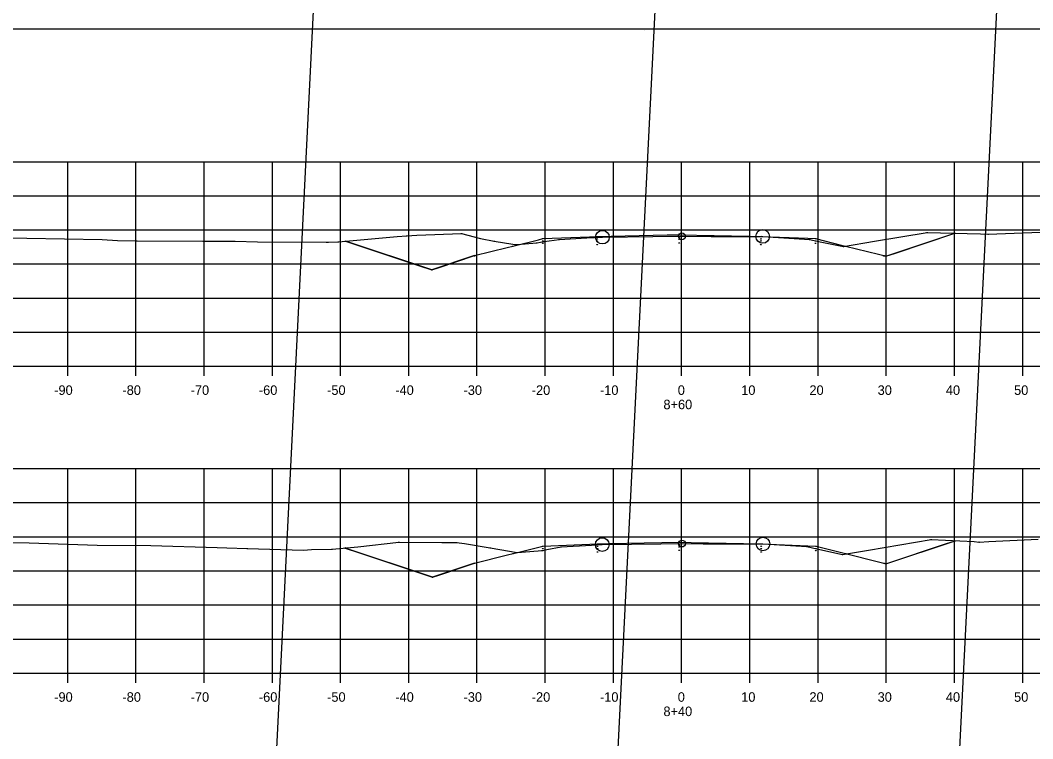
# Model space of a CAD drawing. Extents: x 1300404 to 1323571, y 234004 to 252077.
# Drawn here: x 1315620.3 to 1315768.7, y 242873.8 to 242979.2 of the extents above; entities that cross this region are included whole.
import ezdxf

# ---------------------------------------------------------------- set-up
doc = ezdxf.new("R2010")
doc.units = 0
for name, color, linetype in [('Default', 7, 'Continuous'), ('R_Axis', 7, 'Continuous'), ('R_Axis Annot', 7, 'Continuous'), ('R_Border', 7, 'Continuous'), ('R_Draft', 7, 'Continuous'), ('R_Exist Surface', 7, 'Continuous'), ('R_Fin Surface', 7, 'Continuous'), ('R_Floodway', 7, 'Continuous'), ('R_Grid', 7, 'Continuous'), ('R_No Plot', 7, 'Continuous')]:
    doc.layers.add(name, color=color, linetype=linetype)

msp = doc.modelspace()

# ---------------------------------------------------------------- linework, layer by layer
at = {"layer": 'Default'}
msp.add_line((1315559.28, 242977.92), (1315875.46, 242977.92), dxfattribs=at)
at = {"layer": 'R_Axis'}
for p, q in [((1315577.28, 242928.46), (1315857.28, 242928.46)), ((1315627.28, 242927.06), (1315627.28, 242928.46)), ((1315637.28, 242927.06), (1315637.28, 242928.46)), ((1315647.28, 242927.06), (1315647.28, 242928.46)), ((1315657.28, 242927.06), (1315657.28, 242928.46)), ((1315667.28, 242927.06), (1315667.28, 242928.46)), ((1315677.28, 242927.06), (1315677.28, 242928.46)), ((1315687.28, 242927.06), (1315687.28, 242928.46)), ((1315697.28, 242927.06), (1315697.28, 242928.46)), ((1315707.28, 242927.06), (1315707.28, 242928.46)), ((1315717.28, 242927.06), (1315717.28, 242928.46)), ((1315727.28, 242927.06), (1315727.28, 242928.46)), ((1315737.28, 242927.06), (1315737.28, 242928.46)), ((1315747.28, 242927.06), (1315747.28, 242928.46)), ((1315757.28, 242927.06), (1315757.28, 242928.46)), ((1315767.28, 242927.06), (1315767.28, 242928.46)), ((1315577.28, 242883.46), (1315857.28, 242883.46)), ((1315627.28, 242882.06), (1315627.28, 242883.46)), ((1315637.28, 242882.06), (1315637.28, 242883.46)), ((1315647.28, 242882.06), (1315647.28, 242883.46)), ((1315657.28, 242882.06), (1315657.28, 242883.46)), ((1315667.28, 242882.06), (1315667.28, 242883.46)), ((1315677.28, 242882.06), (1315677.28, 242883.46)), ((1315687.28, 242882.06), (1315687.28, 242883.46)), ((1315697.28, 242882.06), (1315697.28, 242883.46)), ((1315707.28, 242882.06), (1315707.28, 242883.46)), ((1315717.28, 242882.06), (1315717.28, 242883.46)), ((1315727.28, 242882.06), (1315727.28, 242883.46)), ((1315737.28, 242882.06), (1315737.28, 242883.46)), ((1315747.28, 242882.06), (1315747.28, 242883.46)), ((1315757.28, 242882.06), (1315757.28, 242883.46)), ((1315767.28, 242882.06), (1315767.28, 242883.46))]:
    msp.add_line(p, q, dxfattribs=at)
at = {"layer": 'R_Border'}
msp.add_line((1315711.8, 242977.66), (1315711.8, 242977.66), dxfattribs=at)
msp.add_line((1315711.8, 242977.66), (1315711.8, 242977.66), dxfattribs=at)
at = {"layer": 'R_Draft'}
for points in [[(1315637.35, 242946.91), (1315637.4, 242946.81), (1315637.3, 242946.81)], [(1315668.02, 242946.87), (1315668.07, 242946.77), (1315667.97, 242946.77)], [(1315668.02, 242946.87), (1315668.07, 242946.77), (1315667.97, 242946.77)], [(1315677, 242947.65), (1315677.05, 242947.55), (1315676.95, 242947.55)], [(1315685.02, 242947.98), (1315685.07, 242947.88), (1315684.97, 242947.88)], [(1315696.91, 242947.23), (1315696.96, 242947.13), (1315696.86, 242947.13)], [(1315696.91, 242946.9), (1315696.96, 242946.8), (1315696.86, 242946.8)], [(1315699.33, 242947.12), (1315699.38, 242947.02), (1315699.28, 242947.02)], [(1315704.91, 242947.55), (1315704.96, 242947.45), (1315704.86, 242947.45)], [(1315704.91, 242947.22), (1315704.96, 242947.12), (1315704.86, 242947.12)], [(1315704.91, 242946.88), (1315704.96, 242946.78), (1315704.86, 242946.78)], [(1315716.91, 242947.79), (1315716.96, 242947.69), (1315716.86, 242947.69)], [(1315716.91, 242947.46), (1315716.96, 242947.36), (1315716.86, 242947.36)], [(1315716.91, 242947.13), (1315716.96, 242947.03), (1315716.86, 242947.03)], [(1315728.91, 242947.55), (1315728.96, 242947.45), (1315728.86, 242947.45)], [(1315728.91, 242947.22), (1315728.96, 242947.12), (1315728.86, 242947.12)], [(1315728.91, 242946.89), (1315728.96, 242946.79), (1315728.86, 242946.79)], [(1315736.04, 242947.11), (1315736.09, 242947.01), (1315735.99, 242947.01)], [(1315736.91, 242947.23), (1315736.96, 242947.13), (1315736.86, 242947.13)], [(1315736.91, 242946.9), (1315736.96, 242946.8), (1315736.86, 242946.8)], [(1315753.27, 242948.12), (1315753.32, 242948.02), (1315753.22, 242948.02)], [(1315757.34, 242948.02), (1315757.39, 242947.92), (1315757.29, 242947.92)], [(1315757.34, 242948.02), (1315757.39, 242947.92), (1315757.29, 242947.92)], [(1315762.19, 242947.89), (1315762.24, 242947.79), (1315762.14, 242947.79)], [(1315666.98, 242946.78), (1315667.03, 242946.68), (1315666.93, 242946.68)], [(1315689.81, 242946.85), (1315689.86, 242946.75), (1315689.76, 242946.75)], [(1315692.54, 242946.14), (1315692.59, 242946.04), (1315692.49, 242946.04)], [(1315692.87, 242946.36), (1315692.92, 242946.26), (1315692.82, 242946.26)], [(1315696.03, 242946.59), (1315696.08, 242946.49), (1315695.98, 242946.49)], [(1315696.91, 242946.57), (1315696.96, 242946.47), (1315696.86, 242946.47)], [(1315704.91, 242946.38), (1315704.96, 242946.28), (1315704.86, 242946.28)], [(1315716.91, 242946.62), (1315716.96, 242946.52), (1315716.86, 242946.52)], [(1315728.91, 242946.38), (1315728.96, 242946.28), (1315728.86, 242946.28)], [(1315736.91, 242946.57), (1315736.96, 242946.47), (1315736.86, 242946.47)], [(1315741, 242946.09), (1315741.05, 242945.99), (1315740.95, 242945.99)], [(1315741.29, 242946.14), (1315741.34, 242946.04), (1315741.24, 242946.04)], [(1315686.91, 242944.73), (1315686.96, 242944.63), (1315686.86, 242944.63)], [(1315746.91, 242944.73), (1315746.96, 242944.63), (1315746.86, 242944.63)], [(1315747.2, 242944.64), (1315747.25, 242944.54), (1315747.15, 242944.54)], [(1315680.67, 242942.65), (1315680.72, 242942.55), (1315680.62, 242942.55)], [(1315675.8, 242902.7), (1315675.85, 242902.6), (1315675.75, 242902.6)], [(1315684.29, 242902.68), (1315684.34, 242902.58), (1315684.24, 242902.58)], [(1315704.93, 242902.46), (1315704.98, 242902.36), (1315704.88, 242902.36)], [(1315716.93, 242902.7), (1315716.98, 242902.6), (1315716.88, 242902.6)], [(1315716.93, 242902.37), (1315716.98, 242902.27), (1315716.88, 242902.27)], [(1315728.93, 242902.46), (1315728.98, 242902.36), (1315728.88, 242902.36)], [(1315753.85, 242903.09), (1315753.9, 242902.99), (1315753.8, 242902.99)], [(1315757.37, 242902.93), (1315757.42, 242902.83), (1315757.32, 242902.83)], [(1315757.37, 242902.93), (1315757.42, 242902.83), (1315757.32, 242902.83)], [(1315760.89, 242902.74), (1315760.94, 242902.64), (1315760.84, 242902.64)], [(1315653.61, 242901.78), (1315653.66, 242901.68), (1315653.56, 242901.68)], [(1315666.06, 242901.68), (1315666.11, 242901.58), (1315666.01, 242901.58)], [(1315667.98, 242901.86), (1315668.03, 242901.76), (1315667.93, 242901.76)], [(1315667.98, 242901.86), (1315668.03, 242901.76), (1315667.93, 242901.76)], [(1315689.19, 242901.88), (1315689.24, 242901.78), (1315689.14, 242901.78)], [(1315692.56, 242901.05), (1315692.61, 242900.95), (1315692.51, 242900.95)], [(1315693.19, 242901.21), (1315693.24, 242901.11), (1315693.14, 242901.11)], [(1315696.85, 242901.49), (1315696.9, 242901.39), (1315696.8, 242901.39)], [(1315696.93, 242902.14), (1315696.98, 242902.04), (1315696.88, 242902.04)], [(1315696.93, 242901.81), (1315696.98, 242901.71), (1315696.88, 242901.71)], [(1315696.93, 242901.48), (1315696.98, 242901.38), (1315696.88, 242901.38)], [(1315699.63, 242902.04), (1315699.68, 242901.94), (1315699.58, 242901.94)], [(1315704.93, 242902.13), (1315704.98, 242902.03), (1315704.88, 242902.03)], [(1315704.93, 242901.8), (1315704.98, 242901.7), (1315704.88, 242901.7)], [(1315704.93, 242901.3), (1315704.98, 242901.2), (1315704.88, 242901.2)], [(1315716.93, 242902.04), (1315716.98, 242901.94), (1315716.88, 242901.94)], [(1315716.93, 242901.54), (1315716.98, 242901.44), (1315716.88, 242901.44)], [(1315728.93, 242902.13), (1315728.98, 242902.03), (1315728.88, 242902.03)], [(1315728.93, 242901.8), (1315728.98, 242901.7), (1315728.88, 242901.7)], [(1315728.93, 242901.3), (1315728.98, 242901.2), (1315728.88, 242901.2)], [(1315735.62, 242902.08), (1315735.67, 242901.98), (1315735.57, 242901.98)], [(1315736.93, 242902.14), (1315736.98, 242902.04), (1315736.88, 242902.04)], [(1315736.93, 242901.81), (1315736.98, 242901.71), (1315736.88, 242901.71)], [(1315736.93, 242901.48), (1315736.98, 242901.38), (1315736.88, 242901.38)], [(1315740.85, 242900.92), (1315740.9, 242900.82), (1315740.8, 242900.82)], [(1315741.31, 242901.05), (1315741.36, 242900.95), (1315741.26, 242900.95)], [(1315686.93, 242899.64), (1315686.98, 242899.54), (1315686.88, 242899.54)], [(1315746.93, 242899.64), (1315746.98, 242899.54), (1315746.88, 242899.54)], [(1315747.22, 242899.55), (1315747.27, 242899.45), (1315747.17, 242899.45)], [(1315680.77, 242897.59), (1315680.82, 242897.49), (1315680.72, 242897.49)]]:
    msp.add_lwpolyline(points, close=True, dxfattribs=at)
at = {"layer": 'R_Exist Surface'}
for points in [[(1315615.71, 242947.33), (1315632.36, 242947.05), (1315634.59, 242946.92), (1315637.35, 242946.86), (1315647.1, 242946.79), (1315651.82, 242946.82), (1315655.12, 242946.72), (1315665.16, 242946.64), (1315665.5, 242946.64), (1315666.98, 242946.73), (1315675.59, 242947.47), (1315677, 242947.6), (1315678.46, 242947.69), (1315685.02, 242947.93), (1315687.8, 242947.21), (1315689.81, 242946.8), (1315692.54, 242946.37), (1315692.87, 242946.31), (1315693.16, 242946.33), (1315696.03, 242946.54), (1315697.14, 242946.75), (1315699.33, 242947.07), (1315703.39, 242947.27), (1315705.67, 242947.39), (1315713.04, 242947.47), (1315717.31, 242947.52), (1315721.61, 242947.5), (1315729.16, 242947.5), (1315733.79, 242947.2), (1315736.04, 242947.06), (1315737.82, 242946.68), (1315741, 242946.04), (1315745.56, 242946.8), (1315753.27, 242948.07), (1315761.09, 242947.86), (1315762.19, 242947.84), (1315771.14, 242948.16)], [(1315610.92, 242902.73), (1315621.64, 242902.57), (1315631.58, 242902.21), (1315639.45, 242902.16), (1315649.2, 242901.86), (1315650.59, 242901.82), (1315653.61, 242901.73), (1315661.83, 242901.51), (1315663.03, 242901.57), (1315666.06, 242901.63), (1315669.83, 242901.99), (1315675.8, 242902.65), (1315682.15, 242902.6), (1315684.29, 242902.63), (1315685.47, 242902.47), (1315689.19, 242901.83), (1315692.04, 242901.36), (1315693.19, 242901.16), (1315693.8, 242901.21), (1315696.85, 242901.44), (1315697.51, 242901.6), (1315699.63, 242901.99), (1315704.05, 242902.22), (1315705.63, 242902.32), (1315714.21, 242902.42), (1315717.33, 242902.46), (1315720.45, 242902.43), (1315729.2, 242902.4), (1315730.82, 242902.32), (1315735.62, 242902.03), (1315737.08, 242901.69), (1315740.85, 242900.87), (1315744.69, 242901.51), (1315753.85, 242903.04), (1315760.14, 242902.75), (1315760.89, 242902.69), (1315762.29, 242902.75), (1315769.52, 242903.12)]]:
    msp.add_lwpolyline(points, dxfattribs=at)
at = {"layer": 'R_Fin Surface'}
for points in [[(1315668.02, 242946.82), (1315678.83, 242943.21), (1315680.67, 242942.6), (1315681.6, 242942.91), (1315686.91, 242944.68), (1315691.71, 242945.88), (1315692.54, 242946.09), (1315696.28, 242947.02), (1315696.91, 242947.18), (1315703.75, 242947.45), (1315704.91, 242947.5), (1315715.18, 242947.71), (1315716.91, 242947.74), (1315727.19, 242947.53), (1315728.91, 242947.5), (1315735.77, 242947.23), (1315736.91, 242947.18), (1315740.67, 242946.24), (1315741.29, 242946.09), (1315746.12, 242944.88), (1315746.91, 242944.68), (1315746.95, 242944.67), (1315747.2, 242944.59), (1315748.63, 242945.06), (1315757.34, 242947.97)], [(1315667.98, 242901.81), (1315669.89, 242901.17), (1315680.77, 242897.54), (1315681.69, 242897.84), (1315686.93, 242899.59), (1315691.73, 242900.79), (1315692.56, 242901), (1315693.2, 242901.16), (1315696.93, 242902.09), (1315698.1, 242902.14), (1315704.93, 242902.41), (1315706.67, 242902.45), (1315716.93, 242902.65), (1315718.66, 242902.62), (1315728.93, 242902.41), (1315730.08, 242902.37), (1315736.93, 242902.09), (1315737.56, 242901.94), (1315741.31, 242901), (1315746.14, 242899.79), (1315746.93, 242899.59), (1315746.97, 242899.58), (1315747.22, 242899.5), (1315755.94, 242902.41), (1315757.37, 242902.88)]]:
    msp.add_lwpolyline(points, dxfattribs=at)
at = {"layer": 'R_Floodway'}
for p, q in [((1315724.08, 242194.52), (1315766.53, 243041.85)), ((1315673.23, 242178.64), (1315715.45, 243021.54)), ((1315622.37, 242162.75), (1315664.37, 243001.24))]:
    msp.add_line(p, q, dxfattribs=at)
at = {"layer": 'R_Grid'}
for p, q in [((1315577.28, 242958.46), (1315857.28, 242958.46)), ((1315627.28, 242928.46), (1315627.28, 242958.46)), ((1315637.28, 242928.46), (1315637.28, 242958.46)), ((1315647.28, 242928.46), (1315647.28, 242958.46)), ((1315657.28, 242928.46), (1315657.28, 242958.46)), ((1315667.28, 242928.46), (1315667.28, 242958.46)), ((1315677.28, 242928.46), (1315677.28, 242958.46)), ((1315687.28, 242928.46), (1315687.28, 242958.46)), ((1315697.28, 242928.46), (1315697.28, 242958.46)), ((1315707.28, 242928.46), (1315707.28, 242958.46)), ((1315717.28, 242928.46), (1315717.28, 242958.46)), ((1315727.28, 242928.46), (1315727.28, 242958.46)), ((1315737.28, 242928.46), (1315737.28, 242958.46)), ((1315747.28, 242928.46), (1315747.28, 242958.46)), ((1315757.28, 242928.46), (1315757.28, 242958.46)), ((1315767.28, 242928.46), (1315767.28, 242958.46)), ((1315577.28, 242953.46), (1315857.28, 242953.46)), ((1315577.28, 242948.46), (1315857.28, 242948.46)), ((1315577.28, 242943.46), (1315857.28, 242943.46)), ((1315577.28, 242938.46), (1315857.28, 242938.46)), ((1315577.28, 242933.46), (1315857.28, 242933.46)), ((1315577.28, 242928.46), (1315857.28, 242928.46)), ((1315577.28, 242913.46), (1315857.28, 242913.46)), ((1315627.28, 242883.46), (1315627.28, 242913.46)), ((1315637.28, 242883.46), (1315637.28, 242913.46)), ((1315647.28, 242883.46), (1315647.28, 242913.46)), ((1315657.28, 242883.46), (1315657.28, 242913.46)), ((1315667.28, 242883.46), (1315667.28, 242913.46)), ((1315677.28, 242883.46), (1315677.28, 242913.46)), ((1315687.28, 242883.46), (1315687.28, 242913.46)), ((1315697.28, 242883.46), (1315697.28, 242913.46)), ((1315707.28, 242883.46), (1315707.28, 242913.46)), ((1315717.28, 242883.46), (1315717.28, 242913.46)), ((1315727.28, 242883.46), (1315727.28, 242913.46)), ((1315737.28, 242883.46), (1315737.28, 242913.46)), ((1315747.28, 242883.46), (1315747.28, 242913.46)), ((1315757.28, 242883.46), (1315757.28, 242913.46)), ((1315767.28, 242883.46), (1315767.28, 242913.46)), ((1315577.28, 242908.46), (1315857.28, 242908.46)), ((1315577.28, 242903.46), (1315857.28, 242903.46)), ((1315577.28, 242898.46), (1315857.28, 242898.46)), ((1315577.28, 242893.46), (1315857.28, 242893.46)), ((1315577.28, 242888.46), (1315857.28, 242888.46)), ((1315577.28, 242883.46), (1315857.28, 242883.46))]:
    msp.add_line(p, q, dxfattribs=at)
at = {"layer": 'R_No Plot'}
msp.add_lwpolyline([(1315793.2, 242977.92), (1315793.2, 242968.04), (1315828.93, 242968.04), (1315828.93, 242965.12), (1315852.13, 242965.12), (1315852.13, 242943), (1315875.46, 242943), (1315875.46, 242772.46), (1315559.28, 242772.46), (1315559.28, 242977.92)], close=True, dxfattribs=at)
for points in [[(1315746.91, 242944.68), (1315747.2, 242944.59), (1315757.34, 242947.97)], [(1315746.91, 242944.68), (1315747.2, 242944.59), (1315757.34, 242947.97)], [(1315746.91, 242944.68), (1315747.2, 242944.59), (1315757.34, 242947.97)], [(1315746.91, 242944.68), (1315747.2, 242944.59), (1315757.34, 242947.97)], [(1315680.67, 242942.6), (1315668.02, 242946.82)], [(1315686.91, 242944.68), (1315680.67, 242942.6), (1315668.02, 242946.82)], [(1315686.91, 242944.68), (1315680.67, 242942.6), (1315668.02, 242946.82)], [(1315686.91, 242944.68), (1315680.67, 242942.6), (1315668.02, 242946.82)], [(1315686.91, 242944.68), (1315680.67, 242942.6), (1315668.02, 242946.82)], [(1315686.91, 242944.68), (1315680.67, 242942.6), (1315668.02, 242946.82)], [(1315746.93, 242899.59), (1315747.22, 242899.5), (1315757.37, 242902.88)], [(1315746.93, 242899.59), (1315747.22, 242899.5), (1315757.37, 242902.88)], [(1315746.93, 242899.59), (1315747.22, 242899.5), (1315757.37, 242902.88)], [(1315746.93, 242899.59), (1315747.22, 242899.5), (1315757.37, 242902.88)], [(1315680.77, 242897.54), (1315667.98, 242901.81)], [(1315686.93, 242899.59), (1315680.77, 242897.54), (1315667.98, 242901.81)], [(1315686.93, 242899.59), (1315680.77, 242897.54), (1315667.98, 242901.81)], [(1315686.93, 242899.59), (1315680.77, 242897.54), (1315667.98, 242901.81)], [(1315686.93, 242899.59), (1315680.77, 242897.54), (1315667.98, 242901.81)], [(1315686.93, 242899.59), (1315680.77, 242897.54), (1315667.98, 242901.81)]]:
    msp.add_lwpolyline(points, dxfattribs=at)
for centre, radius in [((1315705.67, 242947.39), 1), ((1315729.16, 242947.5), 1), ((1315717.31, 242947.52), 0.5), ((1315705.63, 242902.32), 1), ((1315717.33, 242902.46), 0.5), ((1315729.2, 242902.4), 1)]:
    msp.add_circle(centre, radius, dxfattribs=at)

# ---------------------------------------------------------------- texts
at = {"layer": 'R_Axis Annot'}
for s, p in [('-90', (1315625.31, 242924.26)), ('-80', (1315635.31, 242924.26)), ('-70', (1315645.31, 242924.26)), ('-60', (1315655.31, 242924.26)), ('-50', (1315665.31, 242924.26)), ('-40', (1315675.31, 242924.26)), ('-30', (1315685.31, 242924.26)), ('-20', (1315695.31, 242924.26)), ('-10', (1315705.31, 242924.26)), ('0', (1315716.71, 242924.26)), ('10', (1315726.01, 242924.26)), ('20', (1315736.01, 242924.26)), ('30', (1315746.01, 242924.26)), ('40', (1315756.01, 242924.26)), ('50', (1315766.01, 242924.26)), ('8+60', (1315714.61, 242922.16)), ('-90', (1315625.31, 242879.26)), ('-80', (1315635.31, 242879.26)), ('-70', (1315645.31, 242879.26)), ('-60', (1315655.31, 242879.26)), ('-50', (1315665.31, 242879.26)), ('-40', (1315675.31, 242879.26)), ('-30', (1315685.31, 242879.26)), ('-20', (1315695.31, 242879.26)), ('-10', (1315705.31, 242879.26)), ('0', (1315716.71, 242879.26)), ('10', (1315726.01, 242879.26)), ('20', (1315736.01, 242879.26)), ('30', (1315746.01, 242879.26)), ('40', (1315756.01, 242879.26)), ('50', (1315766.01, 242879.26)), ('8+40', (1315714.61, 242877.16))]:
    msp.add_text(s, height=1.4, dxfattribs=at).set_placement(p)

doc.saveas('drawing.dxf')
